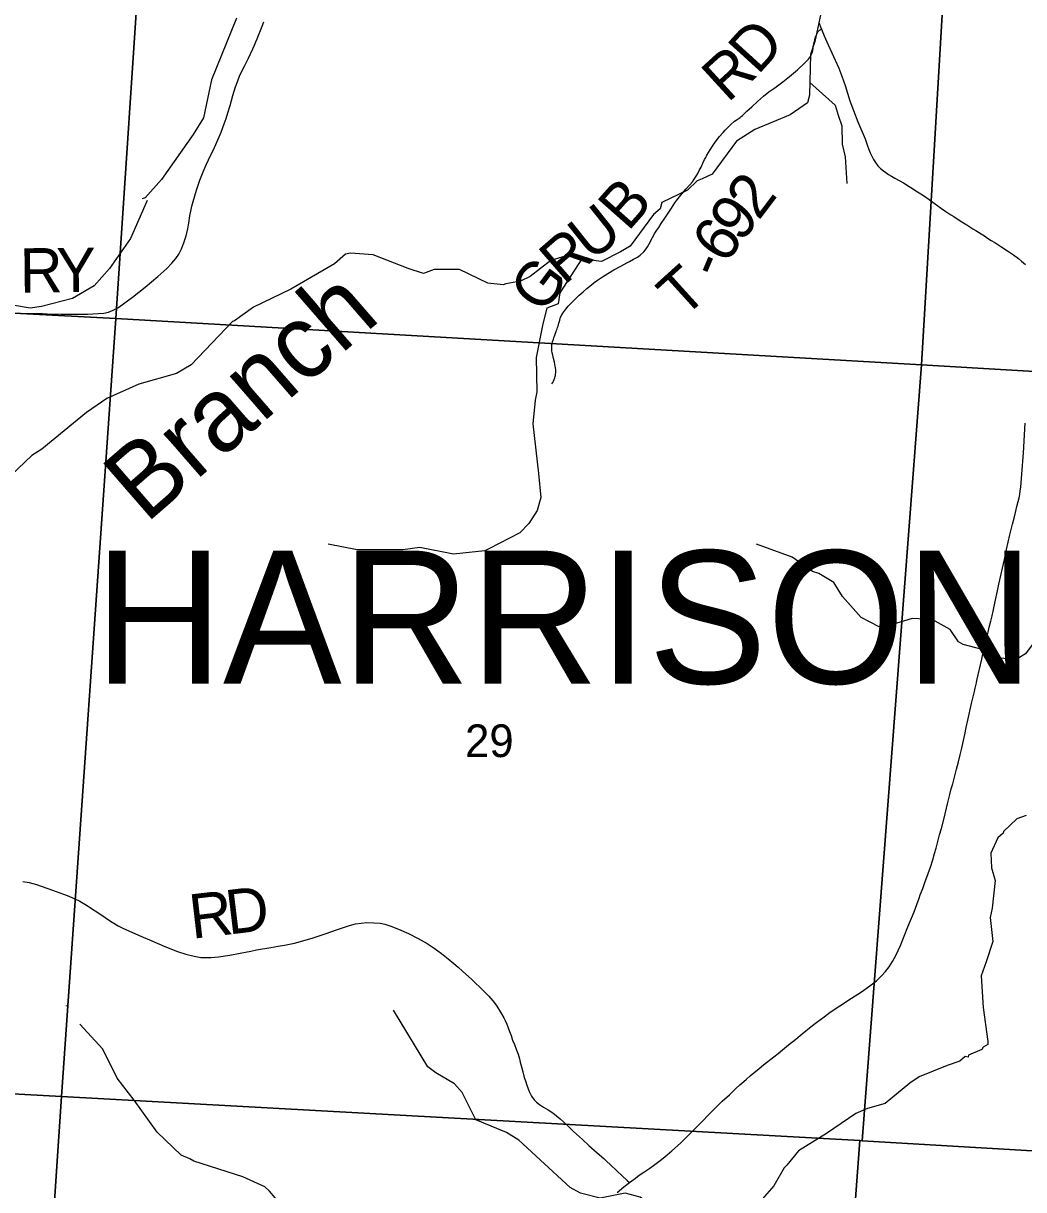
# Model space of a CAD drawing. Extents: x 396.2 to 468.4, y 232.6 to 279.1.
# Drawn here: x 416.488 to 417.769, y 274.409 to 275.903 of the extents above; entities that cross this region are included whole.
import ezdxf

# ---------------------------------------------------------------- set-up
doc = ezdxf.new("R2010")
doc.units = 0
for name, color, linetype in [('GM_X_County_Road', 7, 'Continuous'), ('GM_X_Minor_River', 7, 'Continuous'), ('GM_X_Minor_River_Text', 7, 'Continuous'), ('GM_X_Section', 7, 'Continuous'), ('GM_X_Section_Text', 7, 'Continuous'), ('GM_X_Township_Road', 7, 'Continuous'), ('GM_X_Township_Road_Text', 7, 'Continuous'), ('GM_X_Township_Text', 7, 'Continuous')]:
    doc.layers.add(name, color=color, linetype=linetype)

msp = doc.modelspace()

# ---------------------------------------------------------------- linework, layer by layer
at = {"layer": 'GM_X_County_Road'}
for points in [[(417.2643, 274.4179), (417.2675, 274.4203), (417.272, 274.4237), (417.2769, 274.4273), (417.2843, 274.4323), (417.2903, 274.4364), (417.2969, 274.441), (417.3036, 274.4462), (417.3097, 274.4509), (417.3188, 274.4585), (417.3298, 274.4687), (417.3466, 274.4852), (417.3553, 274.4941), (417.3684, 274.5074), (417.3833, 274.5222), (417.3924, 274.5306), (417.4007, 274.5386), (417.4058, 274.5431), (417.4111, 274.5477), (417.4144, 274.5505), (417.4191, 274.5546), (417.4238, 274.5586), (417.4304, 274.5642), (417.4362, 274.5688), (417.4494, 274.5792), (417.4547, 274.5835), (417.4605, 274.5881), (417.4682, 274.5944), (417.4773, 274.6019), (417.4857, 274.6086), (417.497, 274.6178), (417.5042, 274.6236), (417.5136, 274.6305), (417.5217, 274.6363), (417.5339, 274.6446), (417.5489, 274.6541), (417.5615, 274.6623), (417.5725, 274.6699), (417.5807, 274.6766), (417.5872, 274.6829), (417.5923, 274.6884), (417.597, 274.6943), (417.6014, 274.7012), (417.6055, 274.7089), (417.6114, 274.7219), (417.6211, 274.7455), (417.629, 274.7651), (417.6325, 274.7744), (417.6355, 274.7826), (417.6369, 274.7867), (417.64, 274.795), (417.6428, 274.8024), (417.6472, 274.814), (417.6501, 274.8222), (417.6529, 274.8316), (417.6553, 274.8395), (417.6573, 274.8466), (417.6591, 274.8533), (417.6604, 274.8585), (417.6617, 274.8635), (417.664, 274.8719), (417.6673, 274.8851), (417.6717, 274.9032), (417.6747, 274.9153), (417.6766, 274.9225), (417.6784, 274.9291), (417.6818, 274.941), (417.6834, 274.9476), (417.686, 274.9572), (417.6882, 274.9662), (417.6898, 274.9729), (417.6915, 274.9808), (417.694, 274.9923), (417.6958, 275.0009), (417.6979, 275.0105), (417.7027, 275.0317), (417.704, 275.0371), (417.7063, 275.0472), (417.7074, 275.0516), (417.7088, 275.0583), (417.7095, 275.0613), (417.7156, 275.0886), (417.7181, 275.1001), (417.7198, 275.1068), (417.7217, 275.1149), (417.7237, 275.1231), (417.7253, 275.1297), (417.7272, 275.1375), (417.7288, 275.1444), (417.7301, 275.1502), (417.7328, 275.1626), (417.7358, 275.1763), (417.7377, 275.1848), (417.7446, 275.2164), (417.7473, 275.2291), (417.7516, 275.2479), (417.7528, 275.2533), (417.755, 275.2618), (417.7571, 275.2695), (417.7589, 275.2766), (417.7608, 275.2842), (417.7624, 275.2906), (417.7634, 275.2955), (417.7643, 275.2998), (417.765, 275.3045), (417.7657, 275.3091), (417.7672, 275.3258), (417.769, 275.3531), (417.7714, 275.3909)], [(417.2486, 274.4055), (417.2571, 274.4124), (417.2643, 274.4179)]]:
    msp.add_lwpolyline(points, dxfattribs=at)
at = {"layer": 'GM_X_Minor_River'}
for points in [[(417.4296, 276.188), (417.4355, 276.172), (417.4355, 276.1469), (417.442, 276.1226), (417.4529, 276.0861), (417.476, 276.0306), (417.5101, 275.9569), (417.5132, 275.9345), (417.5018, 275.8801), (417.4961, 275.8633), (417.4949, 275.8112), (417.4923, 275.8014), (417.4703, 275.7861), (417.4252, 275.7674), (417.4016, 275.7522), (417.3702, 275.71), (417.3577, 275.7042), (417.3512, 275.7016), (417.3386, 275.6897)], [(416.7611, 275.91), (416.7289, 275.8308), (416.7186, 275.7822), (416.7057, 275.7609), (416.6648, 275.7034), (416.6439, 275.6798), (416.6401, 275.6787)], [(417.4953, 275.8274), (417.5281, 275.7984), (417.5316, 275.7859), (417.5364, 275.7719), (417.5367, 275.7487), (417.5407, 275.7324), (417.543, 275.6981)], [(417.3387, 275.6897), (417.306, 275.6739), (417.3037, 275.6656), (417.2951, 275.6583), (417.2652, 275.618), (417.2531, 275.6107), (417.2286, 275.5981), (417.1987, 275.6022), (417.1957, 275.6064), (417.1878, 275.6067), (417.1636, 275.5994), (417.1371, 275.5789), (417.1247, 275.5731), (417.1061, 275.5697), (417.1027, 275.5685), (417.0831, 275.5704), (417.0468, 275.5881), (417.0143, 275.5881), (417.0007, 275.5827), (416.981, 275.5891), (416.936, 275.6069), (416.9073, 275.6091), (416.9005, 275.6075), (416.8865, 275.5953), (416.8306, 275.5629), (416.783, 275.5396), (416.7584, 275.5221), (416.7558, 275.5213), (416.7029, 275.466), (416.684, 275.4546), (416.636, 275.4412), (416.5948, 275.4225), (416.5691, 275.4049), (416.5117, 275.3576), (416.4989, 275.3496), (416.4641, 275.3165)], [(416.6465, 275.6762), (416.6252, 275.6278), (416.5985, 275.5893), (416.5789, 275.5672), (416.5509, 275.5507), (416.5115, 275.5407), (416.4967, 275.5383), (416.4743, 275.5424), (416.4359, 275.5608), (416.3658, 275.6045), (416.3311, 275.6199)], [(417.2033, 275.6016), (417.1753, 275.5581), (417.1729, 275.5438), (417.1584, 275.5386), (417.1536, 275.5182), (417.1448, 275.4752), (417.1457, 275.4311), (417.1435, 275.4205), (417.1407, 275.3903), (417.1478, 275.3266), (417.1507, 275.2958), (417.146, 275.2792), (417.1357, 275.2624), (417.124, 275.2507), (417.0844, 275.2299), (417.0791, 275.2274), (417.0389, 275.223), (416.996, 275.2316), (416.974, 275.2289), (416.9158, 275.2288), (416.8786, 275.2361)], [(417.8352, 275.2408), (417.8007, 275.1559), (417.7959, 275.1363), (417.7866, 275.1157), (417.7716, 275.0953), (417.7597, 275.0881), (417.7386, 275.0899), (417.7309, 275.097), (417.6919, 275.1074), (417.6859, 275.111), (417.6754, 275.1265), (417.652, 275.1394), (417.6267, 275.1406), (417.5913, 275.1299), (417.5841, 275.1301), (417.5614, 275.1422), (417.5373, 275.1688), (417.5261, 275.1867), (417.5068, 275.1983), (417.4989, 275.2008), (417.4727, 275.2195), (417.427, 275.2361)], [(417.7724, 274.8883), (417.7607, 274.8841), (417.7433, 274.8677), (417.743, 274.8658), (417.7362, 274.8597), (417.7271, 274.8399), (417.7283, 274.8213), (417.7328, 274.805), (417.7291, 274.7696), (417.7264, 274.7575), (417.7299, 274.7267), (417.7212, 274.7008), (417.7148, 274.6829), (417.7175, 274.6423), (417.7236, 274.5989), (417.7236, 274.5948), (417.7175, 274.5913), (417.7156, 274.5887), (417.6986, 274.5814), (417.6983, 274.5787), (417.6945, 274.5795), (417.6877, 274.5734), (417.6714, 274.568), (417.6355, 274.5535), (417.6235, 274.5455), (417.5921, 274.5195), (417.5691, 274.513), (417.5543, 274.5065), (417.5169, 274.481), (417.481, 274.4588), (417.4659, 274.4402), (417.4625, 274.4371), (417.4493, 274.4139), (417.4342, 274.3968)], [(416.5427, 274.6449), (416.5428, 274.6441)], [(417.3417, 274.3302), (417.2912, 274.3889), (417.2783, 274.3994), (417.2589, 274.4043), (417.2267, 274.398), (417.2016, 274.4043), (417.1886, 274.4115), (417.1226, 274.4723), (417.107, 274.4821), (417.0678, 274.4986), (417.0501, 274.5334), (417.0402, 274.5447), (417.0166, 274.5587), (417.0063, 274.5662), (416.9622, 274.6389)], [(417.0665, 274.0785), (417.019, 274.0939), (416.9758, 274.1147), (416.957, 274.1301), (416.9373, 274.1546), (416.9218, 274.1684), (416.9003, 274.2052), (416.8791, 274.2415), (416.8331, 274.3068), (416.8271, 274.3225), (416.8352, 274.3641), (416.8324, 274.3729), (416.8032, 274.4069), (416.7973, 274.4124), (416.769, 274.4254), (416.7065, 274.4456), (416.7013, 274.4485), (416.6901, 274.453), (416.6596, 274.4824), (416.6299, 274.5236), (416.6084, 274.552), (416.5899, 274.5891), (416.5606, 274.6208), (416.5605, 274.6211)]]:
    msp.add_lwpolyline(points, dxfattribs=at)
at = {"layer": 'GM_X_Section'}
for points in [[(415.6539, 276.603), (416.6739, 276.5403), (416.6066, 275.5251), (415.5888, 275.5786), (415.5983, 275.8171)], [(416.6739, 276.5403), (417.6982, 276.4784), (417.6384, 275.4656), (416.6066, 275.5251)], [(418.7224, 276.4162), (418.6585, 275.4056), (417.6384, 275.4656), (417.6982, 276.4784)], [(415.5888, 275.5786), (416.6066, 275.5251), (416.5371, 274.5285), (415.5204, 274.5839), (415.5344, 274.7946)], [(416.6066, 275.5251), (417.6384, 275.4656), (417.5624, 274.4716), (417.5594, 274.4718), (416.5371, 274.5285)], [(417.6384, 275.4656), (418.6585, 275.4056), (418.6011, 274.4105), (417.5624, 274.4716)], [(415.5204, 274.5839), (416.5371, 274.5285), (416.5087, 274.1071), (416.4804, 273.6869), (416.4687, 273.5133), (415.4502, 273.5695), (415.4623, 273.748)], [(416.5371, 274.5285), (417.5594, 274.4718), (417.5282, 274.0521), (416.5087, 274.1071)], [(417.5594, 274.4718), (417.5624, 274.4716), (418.6011, 274.4105), (418.5769, 274), (417.5282, 274.0521)]]:
    msp.add_lwpolyline(points, close=True, dxfattribs=at)
at = {"layer": 'GM_X_Township_Road'}
for points in [[(416.4863, 275.532), (416.4926, 275.5316), (416.5001, 275.5315), (416.5062, 275.5315), (416.5126, 275.5314), (416.5187, 275.5313), (416.536, 275.5309), (416.5466, 275.5308), (416.5609, 275.5309), (416.5702, 275.5309), (416.5838, 275.5314), (416.5912, 275.5321), (416.5972, 275.5335), (416.6029, 275.5358), (416.6089, 275.5389), (416.6151, 275.543), (416.628, 275.5526), (416.644, 275.5655), (416.6602, 275.579), (416.6717, 275.5893), (416.6782, 275.5959), (416.6833, 275.6021), (416.687, 275.6078), (416.6905, 275.6143), (416.6938, 275.6223), (416.6967, 275.6311), (416.6989, 275.6401), (416.6997, 275.645), (416.7004, 275.6498), (416.7009, 275.6541), (416.7017, 275.6587), (416.7024, 275.6626), (416.7029, 275.665), (416.7039, 275.6689), (416.7054, 275.6752), (416.7097, 275.6894), (416.7141, 275.7023), (416.7183, 275.7133), (416.7221, 275.7219), (416.7283, 275.7347), (416.7307, 275.7397), (416.7346, 275.7481), (416.7413, 275.764), (416.7453, 275.7744), (416.7477, 275.7814), (416.75, 275.7885), (416.7528, 275.798), (416.7564, 275.8108), (416.7596, 275.8222), (416.7626, 275.8299), (416.7655, 275.837), (416.7711, 275.8483), (416.7766, 275.8589), (416.7818, 275.8705), (416.784, 275.8754), (416.7858, 275.8797), (416.7874, 275.8834), (416.7896, 275.889), (416.7916, 275.8942), (416.7962, 275.9051)], [(417.5068, 275.9046), (417.5077, 275.9022), (417.5089, 275.899), (417.5102, 275.8958), (417.5136, 275.8874), (417.519, 275.8759), (417.5237, 275.8655), (417.5281, 275.8562), (417.5324, 275.8459), (417.5365, 275.8358), (417.5408, 275.8239), (417.5468, 275.8039), (417.5514, 275.7915), (417.5571, 275.7771), (417.5662, 275.7553), (417.5688, 275.7478), (417.5709, 275.7418), (417.5729, 275.7374), (417.5747, 275.7333), (417.5771, 275.7291), (417.5794, 275.7252), (417.5827, 275.7207), (417.5858, 275.7175), (417.5896, 275.7143), (417.5927, 275.7122), (417.5963, 275.7097), (417.6, 275.7075), (417.6042, 275.7051), (417.6156, 275.6989), (417.6227, 275.6945), (417.6268, 275.6919), (417.6314, 275.6888), (417.6355, 275.6862), (417.6411, 275.6826), (417.6482, 275.6777), (417.6547, 275.673), (417.6643, 275.6661), (417.6683, 275.6633), (417.676, 275.658), (417.6797, 275.6557), (417.688, 275.6503), (417.6943, 275.6463), (417.6964, 275.645), (417.7043, 275.6401), (417.7079, 275.6378), (417.7148, 275.6335), (417.719, 275.6309), (417.7232, 275.6283), (417.7278, 275.6253), (417.7326, 275.6225), (417.7336, 275.6218), (417.7403, 275.6174), (417.7488, 275.6117), (417.7562, 275.6067), (417.7626, 275.6019), (417.7666, 275.5985), (417.7715, 275.5944)], [(417.1649, 275.4413), (417.1661, 275.4432), (417.167, 275.445), (417.1681, 275.4471), (417.169, 275.4493), (417.1693, 275.4507), (417.1695, 275.4521), (417.1697, 275.4538), (417.17, 275.4557), (417.17, 275.4579), (417.17, 275.46), (417.1694, 275.4643), (417.1683, 275.4691), (417.167, 275.4739), (417.1661, 275.4781), (417.1654, 275.481), (417.1651, 275.4839), (417.1649, 275.4864), (417.165, 275.4892), (417.1651, 275.4911), (417.1659, 275.4952), (417.167, 275.4986), (417.1676, 275.5003), (417.1689, 275.5038), (417.1697, 275.5063), (417.1704, 275.5086), (417.1711, 275.5103), (417.1718, 275.512), (417.1723, 275.5136), (417.1729, 275.5155), (417.1739, 275.519), (417.1751, 275.5232), (417.1762, 275.5267), (417.1778, 275.5297), (417.1791, 275.5321), (417.1827, 275.5372), (417.186, 275.5409), (417.189, 275.5441), (417.1938, 275.5489), (417.2, 275.555), (417.2049, 275.5593), (417.2098, 275.5636), (417.2156, 275.5683), (417.2194, 275.5711), (417.2236, 275.5742), (417.23, 275.5785), (417.2365, 275.5828), (417.2446, 275.5874), (417.2533, 275.5922), (417.261, 275.5963), (417.2643, 275.5981), (417.2697, 275.6011), (417.2745, 275.6039), (417.2781, 275.6065), (417.2827, 275.6105), (417.2858, 275.6144), (417.2875, 275.6172), (417.2894, 275.6202), (417.2908, 275.6229), (417.2924, 275.6259), (417.2941, 275.629), (417.2971, 275.6344), (417.2996, 275.6384), (417.3019, 275.6419), (417.305, 275.6468), (417.3097, 275.6539), (417.3182, 275.6665), (417.3225, 275.6732), (417.3251, 275.677), (417.3285, 275.6812), (417.3321, 275.6854), (417.3366, 275.6908), (417.3418, 275.6964), (417.345, 275.7005), (417.3474, 275.7037), (417.3492, 275.7062), (417.3508, 275.709), (417.352, 275.7111), (417.3539, 275.7147), (417.3561, 275.7192), (417.3584, 275.7244), (417.3607, 275.7289), (417.3621, 275.7316), (417.3635, 275.7343), (417.3676, 275.7412), (417.3706, 275.7458), (417.3734, 275.7499), (417.3795, 275.7578), (417.3843, 275.7635), (417.3871, 275.7666), (417.3893, 275.7688), (417.3914, 275.7709), (417.3944, 275.7738), (417.399, 275.7779), (417.4011, 275.7793), (417.4037, 275.7811), (417.406, 275.7827), (417.4077, 275.7841), (417.4093, 275.7853), (417.4108, 275.7868), (417.4148, 275.7907), (417.4211, 275.7965), (417.4283, 275.8033), (417.436, 275.8099), (417.4428, 275.8154), (417.4508, 275.8209), (417.4608, 275.8283), (417.4696, 275.8352), (417.4796, 275.844), (417.4892, 275.8529), (417.4936, 275.8576), (417.4961, 275.8607), (417.4973, 275.8632), (417.4981, 275.8649), (417.4987, 275.8668), (417.4992, 275.8686), (417.4996, 275.8714), (417.4999, 275.8733), (417.5003, 275.8753), (417.5008, 275.8782), (417.5017, 275.8823), (417.5028, 275.886), (417.5047, 275.8903), (417.5063, 275.893), (417.508, 275.8947), (417.5102, 275.8958)], [(416.4874, 274.8037), (416.4954, 274.8027), (416.505, 274.8), (416.5255, 274.7928), (416.5441, 274.7859), (416.5533, 274.782), (416.5605, 274.7785), (416.5691, 274.7735), (416.5897, 274.7596), (416.5959, 274.7555), (416.6016, 274.7517), (416.6097, 274.7471), (416.6164, 274.7437), (416.6385, 274.7339), (416.6527, 274.7277), (416.6693, 274.7206), (416.6854, 274.7142), (416.6961, 274.7106), (416.7069, 274.7079), (416.7155, 274.7066), (416.7217, 274.7063), (416.7285, 274.7064), (416.7378, 274.7074), (416.7525, 274.7096), (416.7658, 274.7121), (416.7725, 274.7134), (416.7793, 274.7146), (416.7866, 274.7161), (416.8049, 274.7191), (416.8143, 274.7209), (416.8225, 274.7224), (416.8353, 274.7249), (416.8461, 274.7276), (416.8592, 274.7315), (416.8745, 274.7367), (416.8903, 274.7423), (416.9056, 274.7474), (416.9134, 274.7494), (416.9208, 274.7506), (416.9282, 274.7511), (416.9369, 274.751), (416.9449, 274.7503), (416.9509, 274.749), (416.9586, 274.7466), (416.9684, 274.7429), (416.9814, 274.737), (416.9936, 274.7309), (417.0055, 274.7242), (417.0143, 274.7185), (417.0237, 274.7116), (417.0324, 274.7046), (417.0394, 274.6989), (417.0451, 274.6941), (417.0507, 274.6891), (417.0625, 274.6781), (417.0775, 274.6638), (417.0842, 274.6568), (417.0894, 274.651), (417.0935, 274.6453), (417.0979, 274.6385), (417.1007, 274.6342), (417.1034, 274.6293), (417.1051, 274.6258), (417.1074, 274.6209), (417.1091, 274.6163), (417.1108, 274.6116), (417.1127, 274.6064), (417.1148, 274.6005), (417.117, 274.5951), (417.1194, 274.589), (417.1217, 274.5826), (417.1234, 274.5767), (417.1246, 274.5721), (417.126, 274.5665), (417.1277, 274.5601), (417.1296, 274.5528), (417.1311, 274.5482), (417.1328, 274.5428), (417.136, 274.5347), (417.1391, 274.5286), (417.1423, 274.5242), (417.1454, 274.5211), (417.1492, 274.5181), (417.1545, 274.5148), (417.1601, 274.5113), (417.1662, 274.5072), (417.1711, 274.5035), (417.1758, 274.4995), (417.1805, 274.4952), (417.1857, 274.4904), (417.1929, 274.4835), (417.2042, 274.473), (417.2125, 274.4655), (417.2232, 274.4561), (417.2314, 274.4487), (417.235, 274.4454), (417.2403, 274.4406), (417.2483, 274.4332), (417.2613, 274.4208), (417.2643, 274.4179)]]:
    msp.add_lwpolyline(points, dxfattribs=at)

# ---------------------------------------------------------------- texts
at = {"layer": 'GM_X_Minor_River_Text'}
msp.add_text('Branch', height=0.0947, rotation=41.0023, dxfattribs=at).set_placement((416.6448, 275.2612))
at = {"layer": 'GM_X_Section_Text'}
msp.add_text('29', height=0.04186, rotation=0, dxfattribs=at).set_placement((417.0538, 274.9632))
at = {"layer": 'GM_X_Township_Road_Text'}
for s, rotation, p in [('D', 47.7714, (417.4287, 275.8361)), ('R', 42.4615, (417.3902, 275.8006)), ('B', 48.5013, (417.2625, 275.6356)), ('2', 52.9108, (417.4298, 275.6497)), ('U', 38.4729, (417.2155, 275.5971)), ('9', 51.4808, (417.4071, 275.6211)), ('6', 55.2491, (417.3877, 275.5931)), ('R', 40.8885, (417.1807, 275.5669)), ('R', 0.6348, (416.4838, 275.5583)), ('Y', 0.6354, (416.5305, 275.5588)), ('G', 53.0904, (417.1529, 275.5293)), ('-', 67.0355, (417.3801, 275.5744)), ('T', 42.1503, (417.3331, 275.5241)), ('R', 6.6225, (416.7041, 274.7303)), ('D', 6.9108, (416.7508, 274.7357))]:
    msp.add_text(s, height=0.0568, rotation=rotation, dxfattribs=at).set_placement(p)
at = {"layer": 'GM_X_Township_Text'}
msp.add_text('HARRISON', height=0.17045, rotation=0, dxfattribs=at).set_placement((416.5792, 275.0573))

doc.saveas('drawing.dxf')
